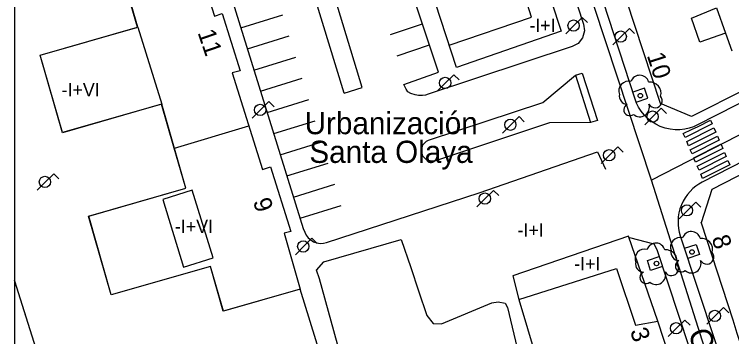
# Model space of a CAD drawing. Extents: x 282771 to 285132, y 4823109 to 4825496.
# Drawn here: x 282771.5 to 282852.4, y 4824148.8 to 4824185.1 of the extents above; entities that cross this region are included whole.
import ezdxf

# ---------------------------------------------------------------- set-up
doc = ezdxf.new("R2010")
doc.units = 0
for name, color, linetype in [('ACERA-BORDILLO', 7, 'Continuous'), ('ACERA-INTERIOR', 7, 'Continuous'), ('APARCAMIENTO', 7, 'Continuous'), ('ARBOL', 7, 'Continuous'), ('BORDILLO', 7, 'Continuous'), ('CALLE-EJE', 7, 'Continuous'), ('CALLE-TEXTO', 7, 'Continuous'), ('Default', 7, 'Continuous'), ('EDIFICIO', 7, 'Continuous'), ('FAROLA', 7, 'Continuous'), ('INTERIOR-EDIFICIO', 7, 'Continuous'), ('MEDIANERA', 7, 'Continuous'), ('NUM-PORTAL', 7, 'Continuous'), ('PASO-PEATONES', 7, 'Continuous'), ('TXT-ALTURA-EDIFICIO', 7, 'Continuous'), ('URBANIZACION-TEXTO', 7, 'Continuous'), ('ZONA-VERDE', 7, 'Continuous')]:
    doc.layers.add(name, color=color, linetype=linetype)

msp = doc.modelspace()

# ---------------------------------------------------------------- linework, layer by layer
at = {"layer": 'ACERA-BORDILLO'}
for points in [[(282799.161, 4824295.551), (282835.662, 4824184.021), (282835.757, 4824183.279), (282835.546, 4824182.497), (282835.042, 4824181.863), (282834.387, 4824181.5), (282818.161, 4824176.147), (282817.829, 4824176.041), (282817.497, 4824176.001), (282817.071, 4824175.987), (282816.672, 4824176.067), (282816.181, 4824176.227), (282815.848, 4824176.413), (282815.649, 4824176.692), (282815.401, 4824177.212), (282819.311, 4824178.632), (282809.841, 4824207.062), (282806.451, 4824206.062), (282804.831, 4824211.152), (282801.568, 4824221.454), (282805.701, 4824222.822), (282805.001, 4824225.632), (282797.261, 4824251.381)], [(282879.24, 4824188.332), (282848.494, 4824172.664), (282848.052, 4824172.465), (282847.573, 4824172.304), (282847.063, 4824172.19), (282846.527, 4824172.128), (282845.974, 4824172.125), (282845.414, 4824172.185), (282844.856, 4824172.309), (282844.314, 4824172.498), (282843.796, 4824172.748), (282843.313, 4824173.053), (282842.874, 4824173.407), (282842.485, 4824173.799), (282842.149, 4824174.221), (282841.869, 4824174.662), (282841.643, 4824175.114), (282841.471, 4824175.567), (282802.311, 4824295.551)], [(282776.971, 4824248.201), (282804.061, 4824160.982), (282804.229, 4824160.567), (282804.388, 4824160.254), (282804.613, 4824159.959), (282804.901, 4824159.702), (282805.238, 4824159.502), (282805.609, 4824159.372), (282805.99, 4824159.317), (282806.36, 4824159.334), (282806.703, 4824159.413), (282823.891, 4824165.012), (282837.231, 4824169.622), (282838.141, 4824167.692)], [(282879.21, 4824181.652), (282849.03, 4824166.202), (282848.671, 4824165.999), (282848.32, 4824165.76), (282847.984, 4824165.486), (282847.667, 4824165.177), (282847.373, 4824164.836), (282847.109, 4824164.465), (282846.877, 4824164.067), (282846.682, 4824163.649), (282846.527, 4824163.214), (282846.413, 4824162.768), (282846.341, 4824162.318), (282846.31, 4824161.869), (282846.319, 4824161.426), (282846.366, 4824160.995), (282846.448, 4824160.579), (282846.561, 4824160.183), (282858.221, 4824124.893)], [(282840.831, 4824159.972), (282843.581, 4824159.266), (282843.921, 4824158.612), (282854.942, 4824125.262)]]:
    msp.add_lwpolyline(points, dxfattribs=at)
at = {"layer": 'ACERA-INTERIOR'}
for points in [[(282841.591, 4824175.242), (282842.911, 4824175.672), (282842.541, 4824176.812), (282841.211, 4824176.372)], [(282847.031, 4824158.762), (282848.361, 4824159.202), (282848.731, 4824158.062), (282847.401, 4824157.622)], [(282844.551, 4824156.692), (282843.221, 4824156.262), (282842.851, 4824157.402), (282844.181, 4824157.832)]]:
    msp.add_lwpolyline(points, dxfattribs=at)
at = {"layer": 'APARCAMIENTO'}
for p, q in [((282810.718, 4824176.878), (282783.673, 4824265.591)), ((282808.668, 4824176.253), (282781.622, 4824264.966)), ((282808.668, 4824176.253), (282810.718, 4824176.878))]:
    msp.add_line(p, q, dxfattribs=at)
for points in [[(282797.026, 4824183.634), (282801.747, 4824185.096)], [(282813.901, 4824182.854), (282817.498, 4824184.075)], [(282797.767, 4824181.247), (282802.48, 4824182.705)], [(282814.661, 4824180.472), (282818.288, 4824181.703)], [(282798.509, 4824178.859), (282803.213, 4824180.315)], [(282799.25, 4824176.472), (282803.946, 4824177.925)], [(282799.992, 4824174.085), (282804.679, 4824175.535)], [(282800.733, 4824171.697), (282805.412, 4824173.145)], [(282801.475, 4824169.309), (282806.145, 4824170.755)], [(282802.216, 4824166.922), (282806.878, 4824168.365)], [(282802.958, 4824164.535), (282807.611, 4824165.975)], [(282803.699, 4824162.147), (282808.344, 4824163.585)]]:
    msp.add_lwpolyline(points, dxfattribs=at)
at = {"layer": 'ARBOL'}
for centre in [(282842.061, 4824175.972), (282847.881, 4824158.352), (282843.891, 4824157.052)]:
    msp.add_circle(centre, 0.255, dxfattribs=at)
for centre, radius, start, end in [((282841.991, 4824177.232), 1.038, 15.64228, 161.38435), ((282840.731, 4824176.502), 1.097, 75.4318, 200.55608), ((282843.121, 4824176.232), 1.272, 345.03273, 95.79925), ((282840.621, 4824175.932), 0.935, 168.59898, 268.13236), ((282843.731, 4824175.402), 0.797, 208.96247, 38.99103), ((282840.861, 4824174.382), 0.672, 113.73672, 309.4725), ((282842.001, 4824174.682), 1.086, 228.95447, 17.92796), ((282846.551, 4824158.882), 1.097, 75.4318, 200.55608), ((282847.811, 4824159.612), 1.038, 15.64228, 161.38435), ((282848.941, 4824158.612), 1.272, 345.03273, 95.79925), ((282843.821, 4824158.312), 1.038, 15.64228, 161.38435), ((282842.561, 4824157.582), 1.097, 75.4318, 200.55608), ((282844.951, 4824157.312), 1.272, 345.03273, 95.79925), ((282846.441, 4824158.312), 0.935, 168.59898, 268.13236), ((282849.551, 4824157.782), 0.797, 208.96247, 38.99103), ((282842.451, 4824157.012), 0.935, 168.59898, 268.13236), ((282845.561, 4824156.482), 0.797, 208.96247, 38.99103), ((282846.681, 4824156.762), 0.672, 113.73672, 309.4725), ((282847.821, 4824157.062), 1.086, 228.95447, 17.92796), ((282842.691, 4824155.462), 0.672, 113.73672, 309.4725), ((282843.831, 4824155.762), 1.086, 228.95447, 17.92796)]:
    msp.add_arc(centre, radius, start, end, dxfattribs=at)
at = {"layer": 'BORDILLO'}
for points in [[(282834.741, 4824178.288), (282835.508, 4824178.494), (282837.217, 4824173.169), (282836.455, 4824172.946)], [(282818.195, 4824170.95), (282831.057, 4824175.212), (282834.741, 4824178.288)], [(282834.741, 4824178.288), (282836.455, 4824172.946)], [(282836.455, 4824172.946), (282831.817, 4824172.92), (282818.962, 4824168.633), (282818.532, 4824168.572), (282817.968, 4824168.735), (282817.546, 4824169.141), (282817.358, 4824169.792), (282817.546, 4824170.442), (282817.968, 4824170.849), (282818.195, 4824170.95)]]:
    msp.add_lwpolyline(points, dxfattribs=at)
at = {"layer": 'CALLE-EJE'}
for points in [[(282843.321, 4824166.432), (282800.711, 4824295.551), (282794.821, 4824314.791)], [(283000.359, 4824247.161), (282843.321, 4824166.432)], [(282859.311, 4824115.893), (282843.321, 4824166.432)]]:
    msp.add_lwpolyline(points, dxfattribs=at)
at = {"layer": 'Default'}
msp.add_lwpolyline([(285130.1, 4825495.5), (282771.5, 4825495.5), (282771.5, 4823109)], dxfattribs=at)
at = {"layer": 'EDIFICIO'}
for points in [[(282815.731, 4824236.095), (282819.971, 4824223.132), (282822.977, 4824214.034), (282833.151, 4824183.242), (282821.351, 4824179.132), (282811.331, 4824209.802), (282808.121, 4824208.752), (282804.471, 4824219.872), (282813.001, 4824222.672), (282808.221, 4824233.742)], [(282853.941, 4824176.712), (282847.841, 4824173.602), (282844.341, 4824175.082), (282840.511, 4824186.782), (282837.031, 4824197.472), (282840.631, 4824198.612), (282844.681, 4824199.892), (282873.13, 4824214.412)], [(282897.2, 4824135.743), (282946.78, 4824160.202), (282959.97, 4824166.842), (282960.014, 4824166.865), (282942.693, 4824201.244), (282940.014, 4824199.894), (282935.276, 4824209.298), (282934.51, 4824208.902), (282927.1, 4824205.032), (282919.4, 4824201.002), (282913.28, 4824197.812), (282903.79, 4824192.882), (282899.1, 4824190.442), (282894, 4824187.802), (282891.09, 4824186.342), (282879.76, 4824180.562), (282878.12, 4824179.722), (282871.31, 4824176.242), (282865.051, 4824173.032), (282858.541, 4824169.702), (282850.131, 4824165.392), (282848.909, 4824161.648)], [(282790.351, 4824196.672), (282794.061, 4824184.912), (282794.941, 4824185.222), (282796.971, 4824178.772), (282796.061, 4824178.552), (282799.481, 4824167.662), (282800.371, 4824167.942), (282802.661, 4824160.652), (282801.931, 4824160.452), (282803.731, 4824154.152), (282795.061, 4824151.682), (282793.621, 4824156.722), (282782.431, 4824153.512), (282779.881, 4824162.392), (282790.841, 4824165.542), (282788.121, 4824175.022), (282776.941, 4824171.802), (282774.421, 4824180.532), (282785.401, 4824183.702), (282782.571, 4824193.502)], [(282848.909, 4824161.648), (282848.901, 4824161.672), (282848.891, 4824161.592), (282848.909, 4824161.648), (282852.471, 4824150.682), (282852.951, 4824149.202), (282856.161, 4824139.453)], [(282847.311, 4824140.543), (282844.031, 4824150.542), (282840.732, 4824160.148), (282827.671, 4824155.662), (282828.381, 4824152.972), (282831.191, 4824143.552)], [(282778.131, 4824134.213), (282771.5, 4824155.172)]]:
    msp.add_lwpolyline(points, dxfattribs=at)
at = {"layer": 'FAROLA'}
for p, q in [((282835.517, 4824184.799), (282834.577, 4824183.869)), ((282836.107, 4824184.209), (282835.517, 4824184.799)), ((282834.577, 4824183.869), (282833.647, 4824182.929)), ((282840.831, 4824183.552), (282839.891, 4824182.622)), ((282841.421, 4824182.962), (282840.831, 4824183.552)), ((282839.891, 4824182.622), (282838.961, 4824181.682)), ((282821.041, 4824178.332), (282820.101, 4824177.402)), ((282821.631, 4824177.742), (282821.041, 4824178.332)), ((282820.101, 4824177.402), (282819.171, 4824176.462)), ((282800.187, 4824175.295), (282799.247, 4824174.365)), ((282800.777, 4824174.705), (282800.187, 4824175.295)), ((282844.422, 4824174.542), (282843.482, 4824173.612)), ((282845.012, 4824173.952), (282844.422, 4824174.542)), ((282799.247, 4824174.365), (282798.317, 4824173.425)), ((282828.388, 4824173.616), (282827.448, 4824172.686)), ((282828.978, 4824173.026), (282828.388, 4824173.616)), ((282843.482, 4824173.612), (282842.552, 4824172.672)), ((282827.448, 4824172.686), (282826.518, 4824171.746)), ((282839.531, 4824170.182), (282838.591, 4824169.252)), ((282840.121, 4824169.592), (282839.531, 4824170.182)), ((282838.591, 4824169.252), (282837.661, 4824168.312)), ((282775.933, 4824167.172), (282774.993, 4824166.242)), ((282776.523, 4824166.582), (282775.933, 4824167.172)), ((282774.993, 4824166.242), (282774.063, 4824165.302)), ((282825.517, 4824165.291), (282824.577, 4824164.361)), ((282826.107, 4824164.701), (282825.517, 4824165.291)), ((282824.577, 4824164.361), (282823.647, 4824163.421)), ((282848.3, 4824163.971), (282847.36, 4824163.041)), ((282848.89, 4824163.381), (282848.3, 4824163.971)), ((282847.36, 4824163.041), (282846.43, 4824162.101)), ((282805.051, 4824159.899), (282804.111, 4824158.969)), ((282805.641, 4824159.309), (282805.051, 4824159.899)), ((282804.111, 4824158.969), (282803.181, 4824158.029)), ((282851.441, 4824152.072), (282850.501, 4824151.142)), ((282852.031, 4824151.482), (282851.441, 4824152.072)), ((282850.501, 4824151.142), (282849.571, 4824150.202)), ((282847.081, 4824150.672), (282846.141, 4824149.742)), ((282847.671, 4824150.082), (282847.081, 4824150.672)), ((282846.141, 4824149.742), (282845.211, 4824148.802))]:
    msp.add_line(p, q, dxfattribs=at)
for centre in [(282834.537, 4824183.869), (282839.851, 4824182.622), (282820.061, 4824177.402), (282799.207, 4824174.365), (282843.442, 4824173.612), (282827.408, 4824172.686), (282838.551, 4824169.252), (282774.953, 4824166.242), (282824.537, 4824164.361), (282847.32, 4824163.041), (282804.071, 4824158.969), (282850.461, 4824151.142), (282846.101, 4824149.742)]:
    msp.add_circle(centre, 0.637, dxfattribs=at)
at = {"layer": 'INTERIOR-EDIFICIO'}
msp.add_lwpolyline([(282850.632, 4824185.872), (282851.661, 4824183.022), (282848.761, 4824182.012), (282847.841, 4824184.712), (282850.632, 4824185.872)], dxfattribs=at)
at = {"layer": 'MEDIANERA'}
for points in [[(282820.521, 4824181.652), (282829.801, 4824184.822), (282823.953, 4824203.253)], [(282785.401, 4824183.702), (282788.121, 4824175.022)], [(282851.661, 4824183.022), (282852.39, 4824181.006)], [(282789.541, 4824170.052), (282797.931, 4824172.572)], [(282793.911, 4824157.682), (282791.561, 4824165.312), (282788.241, 4824164.282), (282790.581, 4824156.652), (282793.911, 4824157.682)], [(282828.381, 4824152.972), (282839.391, 4824156.472), (282841.501, 4824150.092), (282844.031, 4824150.542)]]:
    msp.add_lwpolyline(points, dxfattribs=at)
at = {"layer": 'PASO-PEATONES'}
for points in [[(282847.102, 4824171.252), (282846.906, 4824171.713), (282847.819, 4824172.173), (282848.583, 4824172.489), (282849.986, 4824173.203), (282850.161, 4824172.793)], [(282847.496, 4824170.331), (282847.299, 4824170.792), (282850.358, 4824172.332), (282850.555, 4824171.872)], [(282847.89, 4824169.41), (282847.693, 4824169.87), (282850.752, 4824171.411), (282850.949, 4824170.95)], [(282848.108, 4824168.899), (282848.087, 4824168.949), (282851.145, 4824170.489), (282851.154, 4824170.47), (282851.343, 4824170.029), (282848.284, 4824168.488)], [(282848.677, 4824167.567), (282848.48, 4824168.028), (282851.539, 4824169.568), (282851.736, 4824169.107)], [(282849.071, 4824166.646), (282848.874, 4824167.106), (282851.933, 4824168.647), (282852.13, 4824168.186)]]:
    msp.add_lwpolyline(points, close=True, dxfattribs=at)
at = {"layer": 'ZONA-VERDE'}
for p, q in [((282785.382, 4824183.689), (282782.552, 4824193.489)), ((282771.5, 4824190.289), (282771.5, 4824155.094)), ((282774.402, 4824180.519), (282785.382, 4824183.689)), ((282776.921, 4824171.789), (282774.402, 4824180.519)), ((282788.102, 4824175.009), (282776.921, 4824171.789)), ((282789.527, 4824170.041), (282788.102, 4824175.009)), ((282790.822, 4824165.529), (282789.527, 4824170.041)), ((282779.861, 4824162.379), (282790.822, 4824165.529)), ((282782.411, 4824153.499), (282779.861, 4824162.379)), ((282806.372, 4824157.219), (282815.092, 4824159.769)), ((282815.092, 4824159.769), (282816.192, 4824156.579)), ((282793.602, 4824156.709), (282782.411, 4824153.499)), ((282795.042, 4824151.669), (282793.602, 4824156.709)), ((282805.562, 4824156.309), (282806.372, 4824157.219)), ((282805.892, 4824155.329), (282805.562, 4824156.309)), ((282816.192, 4824156.579), (282817.052, 4824153.979)), ((282771.5, 4824155.094), (282777.727, 4824135.413)), ((282810.85, 4824137.355), (282805.892, 4824155.329)), ((282803.712, 4824154.139), (282795.042, 4824151.669)), ((282809.087, 4824136.756), (282803.712, 4824154.139)), ((282817.052, 4824153.979), (282818.002, 4824151.179)), ((282819.632, 4824150.239), (282825.312, 4824152.609)), ((282825.312, 4824152.609), (282826.042, 4824152.739)), ((282826.042, 4824152.739), (282826.812, 4824152.579)), ((282826.812, 4824152.579), (282827.082, 4824152.079)), ((282827.082, 4824152.079), (282830.467, 4824137.895)), ((282818.002, 4824151.179), (282818.702, 4824150.289)), ((282818.702, 4824150.289), (282819.632, 4824150.239))]:
    msp.add_line(p, q, dxfattribs=at)

# ---------------------------------------------------------------- texts
at = {"layer": 'CALLE-TEXTO'}
msp.add_text('Calle Ceriñola', height=2.5, rotation=287.55645, dxfattribs=at).set_placement((282847.431, 4824149.298))
at = {"layer": 'NUM-PORTAL'}
for s, rotation, p in [('11', 288.92004, (282792.135, 4824183.082)), ('10', 287.75004, (282842.78, 4824180.511)), ('9', 288.92004, (282798.372, 4824164.06)), ('8', 287.55004, (282850.078, 4824159.92)), ('3', 288.92004, (282840.872, 4824149.439))]:
    msp.add_text(s, height=2, rotation=rotation, dxfattribs=at).set_placement(p)
at = {"layer": 'TXT-ALTURA-EDIFICIO'}
for s, p in [('-I+I', (282829.557, 4824183.152)), ('-I+VI', (282776.829, 4824175.882)), ('-I+VI', (282789.599, 4824160.482)), ('-I+I', (282828.225, 4824160.074)), ('-I+I', (282834.607, 4824156.275))]:
    msp.add_text(s, height=1.5, rotation=0.00004, dxfattribs=at).set_placement(p)
at = {"layer": 'URBANIZACION-TEXTO'}
for s, p in [('Urbanización', (282804.219, 4824171.623)), ('Santa Olaya', (282804.755, 4824168.389))]:
    msp.add_text(s, height=2.5, dxfattribs=at).set_placement(p)

doc.saveas('drawing.dxf')
